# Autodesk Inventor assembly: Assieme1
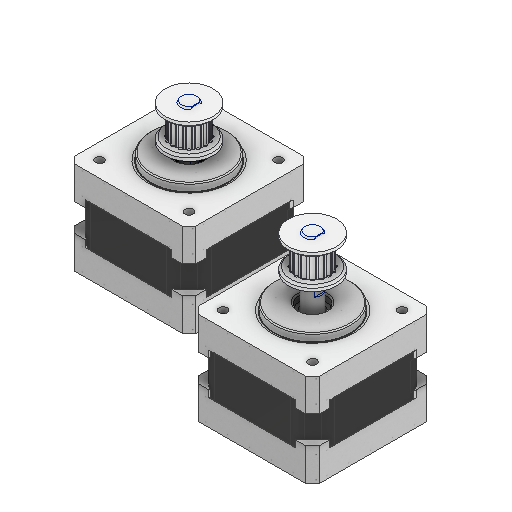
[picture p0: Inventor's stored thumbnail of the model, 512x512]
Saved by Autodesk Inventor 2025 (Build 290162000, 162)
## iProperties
Created: 2025-05
Part Number: Assieme1
Document SubType Name: Assembly
Designer: R5800u
Author: R5800u
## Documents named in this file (3)
- C:\Users\R5800u\Desktop\nema14\Assieme1.iam
- C:\Users\R5800u\Desktop\nema14\NEMA_14-13mm.iam
- C:\Users\R5800u\Desktop\nema14\NEMA_14-18mm.iam
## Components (2 placed, 1 different names)
1. NEMA_14HM11-0404S:1 [sub-assembly]
2. NEMA_14HM11-0404S:2 [sub-assembly]
